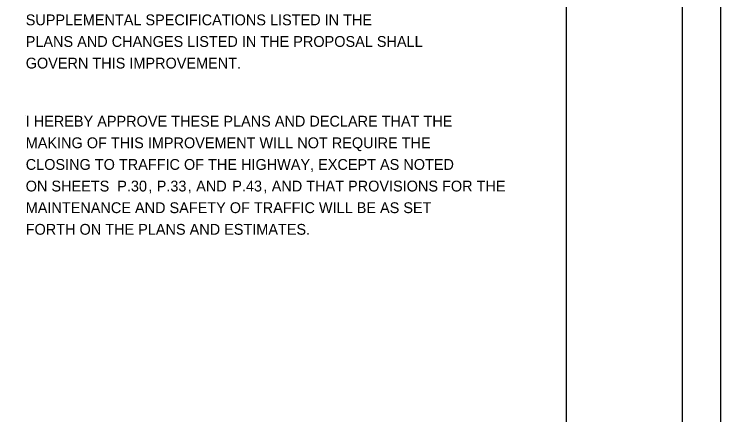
# Model space of a CAD drawing. Extents: x -0.3 to 41.5, y 0 to 22.
# Drawn here: x 24.85 to 34, y 5.19 to 10.38 of the extents above; entities that cross this region are included whole.
import ezdxf

# ---------------------------------------------------------------- set-up
doc = ezdxf.new("R2010")
doc.units = 0
for name, color, linetype in [('GM_X_Section', 7, 'Continuous'), ('SH_Border', 7, 'Continuous'), ('SH_Cut_Line', 7, 'Continuous'), ('SH_Data', 7, 'Continuous')]:
    doc.layers.add(name, color=color, linetype=linetype)

msp = doc.modelspace()

# ---------------------------------------------------------------- linework, layer by layer
at = {"layer": 'SH_Border'}
msp.add_lwpolyline([(0, 0), (34, 0), (34, 22), (0, 22)], close=True, dxfattribs=at)
at = {"layer": 'SH_Cut_Line'}
msp.add_line((25, 9.0605), (25, 9.0605), dxfattribs=at)
at = {"layer": 'SH_Data'}
msp.add_line((32, 0.5), (32, 21.5), dxfattribs=at)
msp.add_lwpolyline([(1.5, 21.5), (33.5, 21.5), (33.5, 0.5), (1.5, 0.5)], close=True, dxfattribs=at)

# ---------------------------------------------------------------- texts
at = {"layer": 'GM_X_Section'}
for s, p in [('SUPPLEMENTAL SPECIFICATIONS LISTED IN THE', (25, 10.2325)), ('PLANS AND CHANGES LISTED IN THE PROPOSAL SHALL', (25, 9.9525)), ('GOVERN THIS IMPROVEMENT.', (25, 9.6725)), ('I HEREBY APPROVE THESE PLANS AND DECLARE THAT THE', (25, 8.9205)), ('MAKING OF THIS IMPROVEMENT WILL NOT REQUIRE THE', (25, 8.6405)), ('CLOSING TO TRAFFIC OF THE HIGHWAY, EXCEPT AS NOTED', (25, 8.3605)), ('ON SHEETS ', (25, 8.0805)), ('P.30', (26.1849, 8.0805)), ('P.33', (26.6958, 8.0805)), ('AND ', (27.2067, 8.0805)), ('P.43', (27.6741, 8.0805)), ('AND THAT PROVISIONS FOR THE', (28.185, 8.0805)), (', ', (26.5872, 8.0805)), (', ', (27.0981, 8.0805)), (', ', (28.0764, 8.0805)), ('MAINTENANCE AND SAFETY OF TRAFFIC WILL BE AS SET', (25, 7.8005)), ('FORTH ON THE PLANS AND ESTIMATES.', (25, 7.5205))]:
    msp.add_text(s, height=0.14, dxfattribs=at).set_placement(p)

doc.saveas('drawing.dxf')
